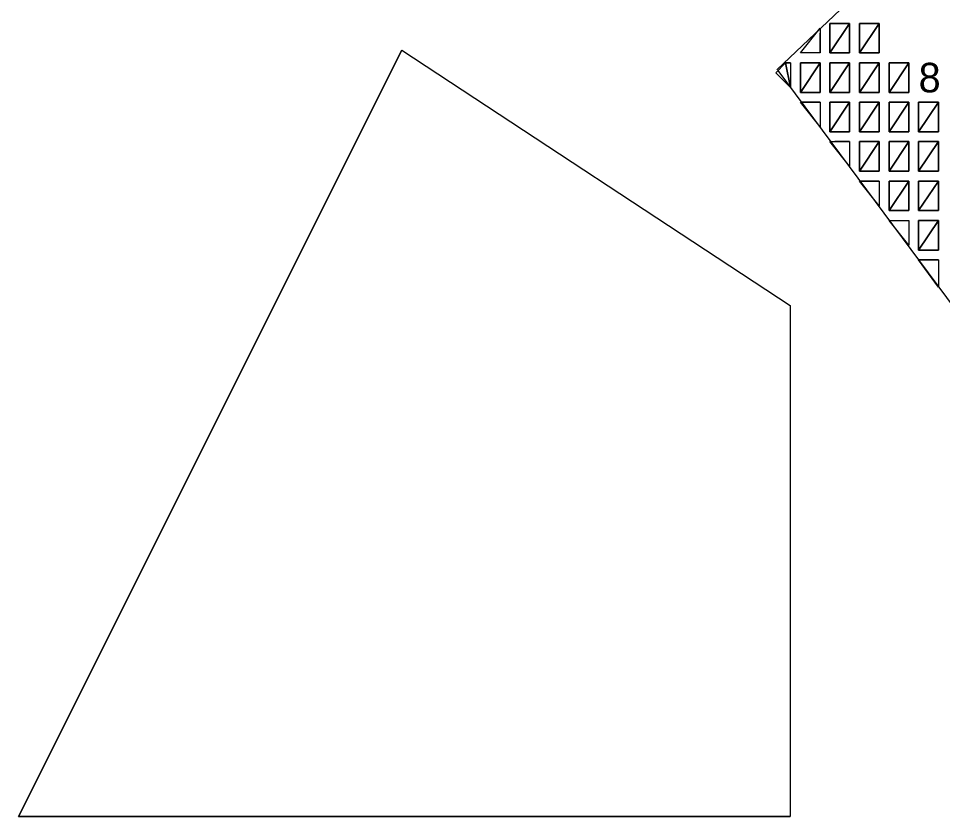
# Model space of a CAD drawing. Extents: x 0 to 44.3, y 0 to 22.
# Drawn here: x 4.3875 to 4.6543, y 1.131 to 1.3615 of the extents above; entities that cross this region are included whole.
import ezdxf

# ---------------------------------------------------------------- set-up
doc = ezdxf.new("R2010")
doc.units = 0
doc.layers.add('Default', color=7, linetype='Continuous')

msp = doc.modelspace()

# ---------------------------------------------------------------- linework, layer by layer
at = {"layer": 'Default'}
for p, q in [((4.78805, 1.51939), (4.60651, 1.34667)), ((4.6275, 1.36004), (4.62181, 1.36004)), ((4.62181, 1.36004), (4.62181, 1.3515)), ((4.6275, 1.3515), (4.6275, 1.36004)), ((4.63604, 1.36004), (4.63034, 1.36004)), ((4.63034, 1.36004), (4.63034, 1.3515)), ((4.63604, 1.3515), (4.63604, 1.36004)), ((4.61896, 1.3515), (4.61896, 1.3572)), ((4.49819, 1.35232), (4.38754, 1.131)), ((4.49819, 1.35232), (4.61034, 1.27857)), ((4.61896, 1.3515), (4.61327, 1.3515)), ((4.62181, 1.3515), (4.6275, 1.3515)), ((4.63034, 1.3515), (4.63604, 1.3515)), ((4.61043, 1.34866), (4.60901, 1.34866)), ((4.61043, 1.34866), (4.61043, 1.34155)), ((4.61896, 1.34866), (4.61327, 1.34866)), ((4.61327, 1.34866), (4.61327, 1.34012)), ((4.61896, 1.34012), (4.61896, 1.34866)), ((4.62181, 1.34866), (4.62181, 1.34012)), ((4.6275, 1.34866), (4.62181, 1.34866)), ((4.6275, 1.34012), (4.6275, 1.34866)), ((4.63604, 1.34866), (4.63034, 1.34866)), ((4.63034, 1.34866), (4.63034, 1.34012)), ((4.63604, 1.34012), (4.63604, 1.34866)), ((4.63888, 1.34866), (4.63888, 1.34012)), ((4.64457, 1.34866), (4.63888, 1.34866)), ((4.64457, 1.34012), (4.64457, 1.34866)), ((4.6068, 1.34644), (4.68687, 1.23853)), ((4.61327, 1.34012), (4.61896, 1.34012)), ((4.62181, 1.34012), (4.6275, 1.34012)), ((4.63034, 1.34012), (4.63604, 1.34012)), ((4.63888, 1.34012), (4.64457, 1.34012)), ((4.61896, 1.33728), (4.61327, 1.33728)), ((4.61896, 1.33728), (4.61896, 1.33017)), ((4.6275, 1.33728), (4.62181, 1.33728)), ((4.62181, 1.33728), (4.62181, 1.32874)), ((4.6275, 1.32874), (4.6275, 1.33728)), ((4.63604, 1.33728), (4.63034, 1.33728)), ((4.63034, 1.33728), (4.63034, 1.32874)), ((4.63604, 1.32874), (4.63604, 1.33728)), ((4.63888, 1.33728), (4.63888, 1.32874)), ((4.64457, 1.33728), (4.63888, 1.33728)), ((4.64457, 1.32874), (4.64457, 1.33728)), ((4.65311, 1.33728), (4.64742, 1.33728)), ((4.64742, 1.33728), (4.64742, 1.32874)), ((4.65311, 1.32874), (4.65311, 1.33728)), ((4.62181, 1.32874), (4.6275, 1.32874)), ((4.63034, 1.32874), (4.63604, 1.32874)), ((4.63888, 1.32874), (4.64457, 1.32874)), ((4.64742, 1.32874), (4.65311, 1.32874)), ((4.6275, 1.3259), (4.62323, 1.3259)), ((4.6275, 1.3259), (4.6275, 1.31879)), ((4.63604, 1.3259), (4.63034, 1.3259)), ((4.63034, 1.3259), (4.63034, 1.31736)), ((4.63604, 1.31736), (4.63604, 1.3259)), ((4.64457, 1.3259), (4.63888, 1.3259)), ((4.63888, 1.3259), (4.63888, 1.31736)), ((4.64457, 1.31736), (4.64457, 1.3259)), ((4.64742, 1.3259), (4.64742, 1.31736)), ((4.65311, 1.3259), (4.64742, 1.3259)), ((4.65311, 1.31736), (4.65311, 1.3259)), ((4.63034, 1.31736), (4.63604, 1.31736)), ((4.63888, 1.31736), (4.64457, 1.31736)), ((4.64742, 1.31736), (4.65311, 1.31736)), ((4.63604, 1.31452), (4.63034, 1.31452)), ((4.63604, 1.31452), (4.63604, 1.3074)), ((4.64457, 1.31452), (4.63888, 1.31452)), ((4.63888, 1.31452), (4.63888, 1.30598)), ((4.64457, 1.30598), (4.64457, 1.31452)), ((4.64742, 1.31452), (4.64742, 1.30598)), ((4.65311, 1.31452), (4.64742, 1.31452)), ((4.65311, 1.30598), (4.65311, 1.31452)), ((4.63888, 1.30598), (4.64457, 1.30598)), ((4.64742, 1.30598), (4.65311, 1.30598)), ((4.63888, 1.30314), (4.64457, 1.30314)), ((4.64457, 1.30314), (4.64457, 1.29602)), ((4.65311, 1.30314), (4.64742, 1.30314)), ((4.64742, 1.30314), (4.64742, 1.2946)), ((4.65311, 1.2946), (4.65311, 1.30314)), ((4.64742, 1.2946), (4.65311, 1.2946)), ((4.65311, 1.29176), (4.64734, 1.29176)), ((4.65311, 1.29176), (4.65311, 1.28408)), ((4.61034, 1.27857), (4.61034, 1.131)), ((4.38754, 1.131), (4.61034, 1.131))]:
    msp.add_line(p, q, dxfattribs=at)
for points in [[(4.61327, 1.3515), (4.61896, 1.35862), (4.61896, 1.3515)], [(4.6275, 1.36004), (4.6275, 1.3515), (4.62181, 1.3515)], [(4.62181, 1.3515), (4.62181, 1.36004), (4.6275, 1.36004)], [(4.6275, 1.36004), (4.6275, 1.36004), (4.6275, 1.36004)], [(4.63034, 1.3515), (4.63034, 1.36004), (4.63604, 1.36004)], [(4.63604, 1.36004), (4.63604, 1.3515), (4.63034, 1.3515)], [(4.63604, 1.36004), (4.63604, 1.36004), (4.63604, 1.36004)], [(4.49819, 1.35232), (4.61034, 1.27857), (4.61034, 1.131), (4.38754, 1.131)], [(4.61043, 1.34155), (4.60616, 1.34581), (4.60901, 1.34866)], [(4.60901, 1.34866), (4.61043, 1.34866), (4.61043, 1.34155)], [(4.61896, 1.34866), (4.61896, 1.34012), (4.61327, 1.34012)], [(4.61327, 1.34012), (4.61327, 1.34866), (4.61896, 1.34866)], [(4.61896, 1.34866), (4.61896, 1.34866), (4.61896, 1.34866)], [(4.62181, 1.34012), (4.62181, 1.34866), (4.6275, 1.34866)], [(4.6275, 1.34866), (4.6275, 1.34012), (4.62181, 1.34012)], [(4.6275, 1.34866), (4.6275, 1.34866), (4.6275, 1.34866)], [(4.63604, 1.34866), (4.63604, 1.34012), (4.63034, 1.34012)], [(4.63034, 1.34012), (4.63034, 1.34866), (4.63604, 1.34866)], [(4.63604, 1.34866), (4.63604, 1.34866), (4.63604, 1.34866)], [(4.63888, 1.34012), (4.63888, 1.34866), (4.64457, 1.34866)], [(4.64457, 1.34866), (4.64457, 1.34012), (4.63888, 1.34012)], [(4.64457, 1.34866), (4.64457, 1.34866), (4.64457, 1.34866)], [(4.61327, 1.33728), (4.61896, 1.33728), (4.61896, 1.33017)], [(4.6275, 1.33728), (4.6275, 1.32874), (4.62181, 1.32874)], [(4.62181, 1.32874), (4.62181, 1.33728), (4.6275, 1.33728)], [(4.6275, 1.33728), (4.6275, 1.33728), (4.6275, 1.33728)], [(4.63034, 1.32874), (4.63034, 1.33728), (4.63604, 1.33728)], [(4.63604, 1.33728), (4.63604, 1.32874), (4.63034, 1.32874)], [(4.63604, 1.33728), (4.63604, 1.33728), (4.63604, 1.33728)], [(4.63888, 1.32874), (4.63888, 1.33728), (4.64457, 1.33728)], [(4.64457, 1.33728), (4.64457, 1.32874), (4.63888, 1.32874)], [(4.64457, 1.33728), (4.64457, 1.33728), (4.64457, 1.33728)], [(4.65311, 1.33728), (4.65311, 1.32874), (4.64742, 1.32874)], [(4.64742, 1.32874), (4.64742, 1.33728), (4.65311, 1.33728)], [(4.65311, 1.33728), (4.65311, 1.33728), (4.65311, 1.33728)], [(4.62181, 1.3259), (4.6275, 1.3259), (4.6275, 1.31879)], [(4.63034, 1.31736), (4.63034, 1.3259), (4.63604, 1.3259)], [(4.63604, 1.3259), (4.63604, 1.31736), (4.63034, 1.31736)], [(4.63604, 1.3259), (4.63604, 1.3259), (4.63604, 1.3259)], [(4.64457, 1.3259), (4.64457, 1.31736), (4.63888, 1.31736)], [(4.63888, 1.31736), (4.63888, 1.3259), (4.64457, 1.3259)], [(4.64457, 1.3259), (4.64457, 1.3259), (4.64457, 1.3259)], [(4.64742, 1.31736), (4.64742, 1.3259), (4.65311, 1.3259)], [(4.65311, 1.3259), (4.65311, 1.31736), (4.64742, 1.31736)], [(4.65311, 1.3259), (4.65311, 1.3259), (4.65311, 1.3259)], [(4.63034, 1.31452), (4.63604, 1.31452), (4.63604, 1.3074)], [(4.63604, 1.31452), (4.63604, 1.31452), (4.63604, 1.31452)], [(4.64457, 1.31452), (4.64457, 1.30598), (4.63888, 1.30598)], [(4.63888, 1.30598), (4.63888, 1.31452), (4.64457, 1.31452)], [(4.64457, 1.31452), (4.64457, 1.31452), (4.64457, 1.31452)], [(4.64742, 1.30598), (4.64742, 1.31452), (4.65311, 1.31452)], [(4.65311, 1.31452), (4.65311, 1.30598), (4.64742, 1.30598)], [(4.65311, 1.31452), (4.65311, 1.31452), (4.65311, 1.31452)], [(4.63888, 1.30314), (4.64457, 1.30314), (4.64457, 1.29602)], [(4.65311, 1.30314), (4.65311, 1.2946), (4.64742, 1.2946)], [(4.64742, 1.2946), (4.64742, 1.30314), (4.65311, 1.30314)], [(4.65311, 1.30314), (4.65311, 1.30314), (4.65311, 1.30314)], [(4.65313, 1.28392), (4.64734, 1.29178), (4.65313, 1.29178)]]:
    msp.add_lwpolyline(points, close=True, dxfattribs=at)

# ---------------------------------------------------------------- texts
msp.add_text('8', height=0.00854, dxfattribs=at).set_placement((4.64742, 1.34012))

doc.saveas('drawing.dxf')
